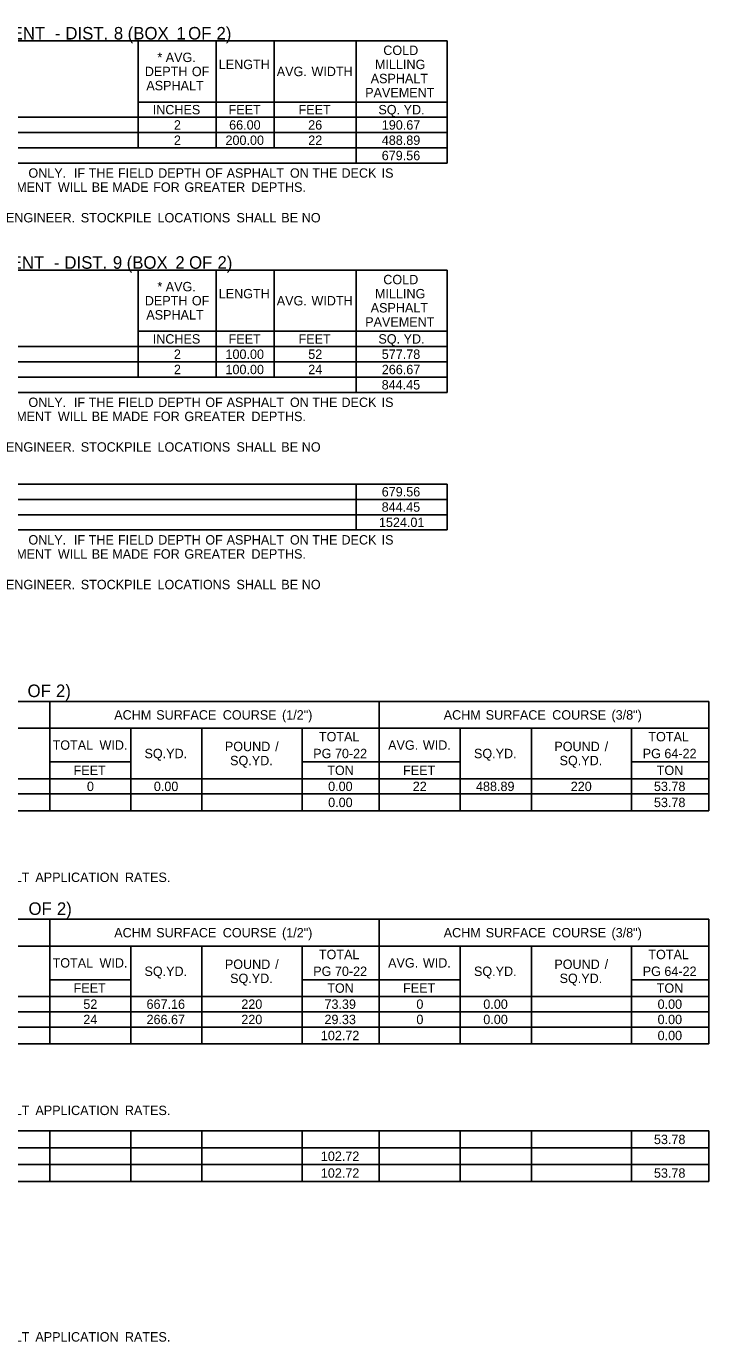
# Model space of a CAD drawing. Extents: x 544420 to 1930787, y -1947044 to 596640.
# Drawn here: x 546901 to 547336, y -1946895 to -1946055 of the extents above; entities that cross this region are included whole.
import ezdxf

# ---------------------------------------------------------------- set-up
doc = ezdxf.new("R2010")
doc.units = 0
doc.layers.add('Default', color=7, linetype='Continuous')

msp = doc.modelspace()

# ---------------------------------------------------------------- linework, layer by layer
at = {"layer": 'Default'}
for p, q in [((546578.54, -1946064.79), (547169.39, -1946064.79)), ((546578.54, -1946064.79), (547169.39, -1946064.79)), ((546972.44, -1946133.04), (546972.44, -1946064.79)), ((547022.16, -1946133.04), (547022.16, -1946064.79)), ((547059.21, -1946133.04), (547059.21, -1946064.79)), ((547111.38, -1946142.79), (547111.38, -1946064.79)), ((547169.39, -1946142.79), (547169.39, -1946064.79)), ((546972.44, -1946103.79), (547059.21, -1946103.79)), ((546972.44, -1946103.79), (547022.16, -1946103.79)), ((547022.16, -1946103.79), (547169.39, -1946103.79)), ((547059.21, -1946113.54), (547059.21, -1946103.79)), ((546578.54, -1946113.54), (547169.39, -1946113.54)), ((546778.41, -1946123.29), (547169.39, -1946123.29)), ((546578.54, -1946133.04), (547169.39, -1946133.04)), ((546578.54, -1946133.04), (547169.39, -1946133.04)), ((546578.54, -1946142.79), (547169.39, -1946142.79)), ((546578.54, -1946211.04), (547169.39, -1946211.04)), ((546578.54, -1946211.04), (547169.39, -1946211.04)), ((546972.44, -1946279.29), (546972.44, -1946211.04)), ((547022.16, -1946279.29), (547022.16, -1946211.04)), ((547059.21, -1946279.29), (547059.21, -1946211.04)), ((547111.38, -1946289.04), (547111.38, -1946211.04)), ((547169.39, -1946289.04), (547169.39, -1946211.04)), ((546972.44, -1946250.04), (547059.21, -1946250.04)), ((546972.44, -1946250.04), (547022.16, -1946250.04)), ((547022.16, -1946250.04), (547169.39, -1946250.04)), ((547059.21, -1946259.79), (547059.21, -1946250.04)), ((546578.54, -1946259.79), (547169.39, -1946259.79)), ((546578.54, -1946269.54), (547169.39, -1946269.54)), ((546578.54, -1946279.29), (547169.39, -1946279.29)), ((546578.54, -1946289.04), (547169.39, -1946289.04)), ((546578.54, -1946347.54), (547169.39, -1946347.54)), ((546578.54, -1946347.54), (547169.39, -1946347.54)), ((547111.38, -1946376.79), (547111.38, -1946347.54)), ((547169.39, -1946376.79), (547169.39, -1946347.54)), ((546578.54, -1946357.29), (547169.39, -1946357.29)), ((546578.54, -1946367.04), (547169.39, -1946367.04)), ((546578.54, -1946376.79), (547169.39, -1946376.79)), ((546342.21, -1946486.24), (547336.23, -1946486.24)), ((546916, -1946555.95), (546916, -1946486.24)), ((547126.11, -1946486.24), (547336.23, -1946486.24)), ((547126.11, -1946555.95), (547126.11, -1946486.24)), ((547336.23, -1946555.95), (547336.23, -1946486.24)), ((546753.66, -1946503.3), (547336.23, -1946503.3)), ((546967.68, -1946503.3), (547013.01, -1946503.3)), ((546967.68, -1946555.95), (546967.68, -1946503.3)), ((547013.01, -1946555.95), (547013.01, -1946503.3)), ((547076.88, -1946555.95), (547076.88, -1946503.3)), ((547177.79, -1946503.3), (547223.13, -1946503.3)), ((547177.79, -1946555.95), (547177.79, -1946503.3)), ((547223.13, -1946555.95), (547223.13, -1946503.3)), ((547286.99, -1946555.95), (547286.99, -1946503.3)), ((546916, -1946524.75), (546967.68, -1946524.75)), ((546916, -1946535.47), (546916, -1946524.75)), ((546967.68, -1946535.47), (546967.68, -1946524.75)), ((547076.88, -1946524.75), (547177.79, -1946524.75)), ((547126.11, -1946535.47), (547126.11, -1946524.75)), ((547177.79, -1946535.47), (547177.79, -1946524.75)), ((547286.99, -1946524.75), (547336.23, -1946524.75)), ((546342.21, -1946535.47), (547336.23, -1946535.47)), ((546847.75, -1946535.47), (546967.68, -1946535.47)), ((546967.68, -1946535.47), (547177.79, -1946535.47)), ((547177.79, -1946535.47), (547336.23, -1946535.47)), ((546342.21, -1946545.22), (547336.23, -1946545.22)), ((546342.21, -1946545.22), (547336.23, -1946545.22)), ((546342.21, -1946555.95), (547336.23, -1946555.95)), ((546342.21, -1946625.17), (547336.23, -1946625.17)), ((546916, -1946704.64), (546916, -1946625.17)), ((547126.11, -1946625.17), (547336.23, -1946625.17)), ((547126.11, -1946704.64), (547126.11, -1946625.17)), ((547336.23, -1946704.64), (547336.23, -1946625.17)), ((546753.66, -1946642.24), (547336.23, -1946642.24)), ((546967.68, -1946642.24), (547013.01, -1946642.24)), ((546967.68, -1946704.64), (546967.68, -1946642.24)), ((547013.01, -1946704.64), (547013.01, -1946642.24)), ((547076.88, -1946704.64), (547076.88, -1946642.24)), ((547177.79, -1946642.24), (547223.13, -1946642.24)), ((547177.79, -1946704.64), (547177.79, -1946642.24)), ((547223.13, -1946704.64), (547223.13, -1946642.24)), ((547286.99, -1946704.64), (547286.99, -1946642.24)), ((546916, -1946663.69), (546967.68, -1946663.69)), ((546916, -1946674.41), (546916, -1946663.69)), ((546967.68, -1946674.41), (546967.68, -1946663.69)), ((547076.88, -1946663.69), (547177.79, -1946663.69)), ((547126.11, -1946674.41), (547126.11, -1946663.69)), ((547177.79, -1946674.41), (547177.79, -1946663.69)), ((547286.99, -1946663.69), (547336.23, -1946663.69)), ((546342.21, -1946674.41), (547336.23, -1946674.41)), ((546847.75, -1946674.41), (546967.68, -1946674.41)), ((546967.68, -1946674.41), (547177.79, -1946674.41)), ((547177.79, -1946674.41), (547336.23, -1946674.41)), ((546342.21, -1946684.16), (547336.23, -1946684.16)), ((546342.21, -1946693.91), (547336.23, -1946693.91)), ((546342.21, -1946704.64), (547336.23, -1946704.64)), ((546342.21, -1946760.21), (547336.23, -1946760.21)), ((546554.76, -1946760.21), (547076.88, -1946760.21)), ((546916, -1946792.39), (546916, -1946760.21)), ((546967.68, -1946792.39), (546967.68, -1946760.21)), ((547013.01, -1946792.39), (547013.01, -1946760.21)), ((547076.88, -1946760.21), (547126.11, -1946760.21)), ((547076.88, -1946792.39), (547076.88, -1946760.21)), ((547126.11, -1946760.21), (547336.23, -1946760.21)), ((547126.11, -1946792.39), (547126.11, -1946760.21)), ((547177.79, -1946792.39), (547177.79, -1946760.21)), ((547223.13, -1946792.39), (547223.13, -1946760.21)), ((547286.99, -1946792.39), (547286.99, -1946760.21)), ((547336.23, -1946792.39), (547336.23, -1946760.21)), ((546342.21, -1946770.94), (547336.23, -1946770.94)), ((546342.21, -1946781.66), (547336.23, -1946781.66)), ((546342.21, -1946792.39), (547336.23, -1946792.39))]:
    msp.add_line(p, q, dxfattribs=at)

# ---------------------------------------------------------------- texts
for s, height, p in [(' PAVEMENT', 8, (546851.26, -1946063.91)), (' DIST.', 8, (546922.99, -1946063.91)), (' 8', 8, (546953.89, -1946063.91)), (' (BOX', 8, (546962.71, -1946063.91)), (' 1', 8, (546993.75, -1946063.91)), (' OF', 8, (547001.25, -1946063.91)), (' 2)', 8, (547019.36, -1946063.91)), (' -', 8, (546916.25, -1946063.91)), ('*', 6, (546984.64, -1946078.29)), (' AVG.', 6, (546987.72, -1946078.29)), ('COLD', 6, (547128.71, -1946073.79)), ('DEPTH', 6, (546976.62, -1946087.29)), (' OF', 6, (547004.4, -1946087.29)), ('LENGTH', 6, (547023.78, -1946082.79)), ('AVG.', 6, (547060.76, -1946087.29)), (' WIDTH', 6, (547080.68, -1946087.29)), ('MILLING', 6, (547123.41, -1946082.79)), ('ASPHALT', 6, (546977.59, -1946096.29)), ('ASPHALT', 6, (547120.67, -1946091.79)), ('PAVEMENT', 6, (547117.18, -1946100.79)), ('INCHES', 6, (546981.67, -1946111.66)), ('FEET', 6, (547030.06, -1946111.66)), ('FEET', 6, (547074.67, -1946111.66)), ('SQ.', 6, (547125.59, -1946111.66)), (' YD.', 6, (547139.45, -1946111.66)), ('2', 6, (546995.19, -1946121.41)), ('66.00', 6, (547030.41, -1946121.41)), ('26', 6, (547080.82, -1946121.41)), ('190.67', 6, (547127.76, -1946121.41)), ('2', 6, (546995.19, -1946131.16)), ('200.00', 6, (547028.08, -1946131.16)), ('22', 6, (547080.86, -1946131.16)), ('488.89', 6, (547127.75, -1946131.16)), ('679.56', 6, (547127.72, -1946140.91)), (' ONLY.', 6, (546900.16, -1946152.09)), ('  IF', 6, (546926.91, -1946152.09)), (' THE', 6, (546938.63, -1946152.09)), (' FIELD', 6, (546957.28, -1946152.09)), (' DEPTH', 6, (546982.92, -1946152.09)), (' OF', 6, (547012.99, -1946152.09)), (' ASPHALT', 6, (547026.57, -1946152.09)), (' ON', 6, (547066.94, -1946152.09)), (' THE', 6, (547081.16, -1946152.09)), (' DECK', 6, (547099.81, -1946152.09)), (' IS', 6, (547125.41, -1946152.09)), (' PAYMENT', 6, (546876.27, -1946161.09)), (' WILL', 6, (546918.96, -1946161.09)), (' BE', 6, (546940.55, -1946161.09)), (' MADE', 6, (546953.62, -1946161.09)), (' FOR', 6, (546979.72, -1946161.09)), (' GREATER', 6, (546999.63, -1946161.09)), (' DEPTHS.', 6, (547042.38, -1946161.09)), (' ENGINEER.', 6, (546885.84, -1946180.59)), (' STOCKPILE', 6, (546933.56, -1946180.59)), (' LOCATIONS', 6, (546982.5, -1946180.59)), (' SHALL', 6, (547032.83, -1946180.59)), (' BE', 6, (547061.43, -1946180.59)), (' NO', 6, (547074.49, -1946180.59)), (' PAVEMENT', 8, (546850.64, -1946210.16)), (' -', 8, (546915.63, -1946210.16)), (' DIST.', 8, (546922.38, -1946210.16)), (' 9', 8, (546953.28, -1946210.16)), (' (BOX', 8, (546962.08, -1946210.16)), (' 2', 8, (546993.11, -1946210.16)), (' OF', 8, (547001.87, -1946210.16)), (' 2)', 8, (547019.98, -1946210.16)), ('COLD', 6, (547128.71, -1946220.04)), ('*', 6, (546984.64, -1946224.54)), (' AVG.', 6, (546987.72, -1946224.54)), ('LENGTH', 6, (547023.78, -1946229.04)), ('MILLING', 6, (547123.41, -1946229.04)), ('DEPTH', 6, (546976.62, -1946233.54)), (' OF', 6, (547004.4, -1946233.54)), ('AVG.', 6, (547060.76, -1946233.54)), (' WIDTH', 6, (547080.68, -1946233.54)), ('ASPHALT', 6, (547120.67, -1946238.04)), ('ASPHALT', 6, (546977.59, -1946242.54)), ('PAVEMENT', 6, (547117.18, -1946247.04)), ('INCHES', 6, (546981.67, -1946257.91)), ('FEET', 6, (547030.06, -1946257.91)), ('FEET', 6, (547074.67, -1946257.91)), ('SQ.', 6, (547125.59, -1946257.91)), (' YD.', 6, (547139.45, -1946257.91)), ('2', 6, (546995.19, -1946267.66)), ('100.00', 6, (547028.08, -1946267.66)), ('52', 6, (547080.86, -1946267.66)), ('577.78', 6, (547127.75, -1946267.66)), ('2', 6, (546995.19, -1946277.41)), ('100.00', 6, (547028.08, -1946277.41)), ('24', 6, (547080.84, -1946277.41)), ('266.67', 6, (547127.76, -1946277.41)), ('844.45', 6, (547127.69, -1946287.16)), (' ONLY.', 6, (546900.16, -1946298.34)), ('  IF', 6, (546926.91, -1946298.34)), (' THE', 6, (546938.63, -1946298.34)), (' FIELD', 6, (546957.28, -1946298.34)), (' DEPTH', 6, (546982.92, -1946298.34)), (' OF', 6, (547012.99, -1946298.34)), (' ASPHALT', 6, (547026.57, -1946298.34)), (' ON', 6, (547066.94, -1946298.34)), (' THE', 6, (547081.16, -1946298.34)), (' DECK', 6, (547099.81, -1946298.34)), (' IS', 6, (547125.41, -1946298.34)), (' PAYMENT', 6, (546876.27, -1946307.34)), (' WILL', 6, (546918.96, -1946307.34)), (' BE', 6, (546940.55, -1946307.34)), (' MADE', 6, (546953.62, -1946307.34)), (' FOR', 6, (546979.72, -1946307.34)), (' GREATER', 6, (546999.63, -1946307.34)), (' DEPTHS.', 6, (547042.38, -1946307.34)), (' ENGINEER.', 6, (546885.84, -1946326.84)), (' STOCKPILE', 6, (546933.56, -1946326.84)), (' LOCATIONS', 6, (546982.5, -1946326.84)), (' SHALL', 6, (547032.83, -1946326.84)), (' BE', 6, (547061.43, -1946326.84)), (' NO', 6, (547074.49, -1946326.84)), ('679.56', 6, (547127.72, -1946355.41)), ('844.45', 6, (547127.69, -1946365.16)), ('1524.01', 6, (547125.92, -1946374.91)), (' ONLY.', 6, (546900.16, -1946386.09)), ('  IF', 6, (546926.91, -1946386.09)), (' THE', 6, (546938.63, -1946386.09)), (' FIELD', 6, (546957.28, -1946386.09)), (' DEPTH', 6, (546982.92, -1946386.09)), (' OF', 6, (547012.99, -1946386.09)), (' ASPHALT', 6, (547026.57, -1946386.09)), (' ON', 6, (547066.94, -1946386.09)), (' THE', 6, (547081.16, -1946386.09)), (' DECK', 6, (547099.81, -1946386.09)), (' IS', 6, (547125.41, -1946386.09)), (' PAYMENT', 6, (546876.27, -1946395.09)), (' WILL', 6, (546918.96, -1946395.09)), (' BE', 6, (546940.55, -1946395.09)), (' MADE', 6, (546953.62, -1946395.09)), (' FOR', 6, (546979.72, -1946395.09)), (' GREATER', 6, (546999.63, -1946395.09)), (' DEPTHS.', 6, (547042.38, -1946395.09)), (' ENGINEER.', 6, (546885.84, -1946414.59)), (' STOCKPILE', 6, (546933.56, -1946414.59)), (' LOCATIONS', 6, (546982.5, -1946414.59)), (' SHALL', 6, (547032.83, -1946414.59)), (' BE', 6, (547061.43, -1946414.59)), (' NO', 6, (547074.49, -1946414.59)), (' OF', 8, (546898.87, -1946483.41)), (' 2)', 8, (546916.98, -1946483.41)), ('ACHM', 6, (546957.12, -1946497.77)), (' SURFACE', 6, (546981.67, -1946497.77)), (' COURSE', 6, (547024.11, -1946497.77)), (' (1/2")', 6, (547061.9, -1946497.77)), ('ACHM', 6, (547167.24, -1946497.77)), (' SURFACE', 6, (547191.79, -1946497.77)), (' COURSE', 6, (547234.22, -1946497.77)), (' (3/8")', 6, (547272.01, -1946497.77)), ('TOTAL', 6, (546917.81, -1946517.02)), (' WID.', 6, (546945.5, -1946517.02)), ('POUND', 6, (547027.68, -1946517.89)), (' /', 6, (547057.54, -1946517.89)), ('TOTAL', 6, (547087.65, -1946511.66)), ('AVG.', 6, (547131.8, -1946517.02)), (' WID.', 6, (547151.72, -1946517.02)), ('POUND', 6, (547237.79, -1946517.89)), (' /', 6, (547267.66, -1946517.89)), ('TOTAL', 6, (547297.76, -1946511.66)), ('SQ.YD.', 6, (546976.42, -1946522.39)), ('PG', 6, (547084.02, -1946522.39)), (' 70-22', 6, (547095.63, -1946522.39)), ('SQ.YD.', 6, (547186.54, -1946522.39)), ('PG', 6, (547294.14, -1946522.39)), (' 64-22', 6, (547305.74, -1946522.39)), ('FEET', 6, (546931.21, -1946533.11)), ('SQ.YD.', 6, (547031.02, -1946526.89)), ('TON', 6, (547092.98, -1946533.11)), ('FEET', 6, (547141.32, -1946533.11)), ('SQ.YD.', 6, (547241.14, -1946526.89)), ('TON', 6, (547303.09, -1946533.11)), ('0', 6, (546939.71, -1946543.35)), ('0.00', 6, (546982.39, -1946543.35)), ('0.00', 6, (547093.54, -1946543.35)), ('22', 6, (547147.51, -1946543.35)), ('488.89', 6, (547187.83, -1946543.35)), ('220', 6, (547248.27, -1946543.35)), ('53.78', 6, (547301.31, -1946543.35)), ('0.00', 6, (547093.55, -1946553.59)), ('53.78', 6, (547301.31, -1946553.59)), (' ASPHALT', 6, (546864.24, -1946601.36)), (' APPLICATION', 6, (546904.61, -1946601.36)), (' RATES.', 6, (546961.69, -1946601.36)), (' OF', 8, (546899.48, -1946622.35)), (' 2)', 8, (546917.59, -1946622.35)), ('ACHM', 6, (546957.12, -1946636.7)), (' SURFACE', 6, (546981.67, -1946636.7)), (' COURSE', 6, (547024.11, -1946636.7)), (' (1/2")', 6, (547061.9, -1946636.7)), ('ACHM', 6, (547167.24, -1946636.7)), (' SURFACE', 6, (547191.79, -1946636.7)), (' COURSE', 6, (547234.22, -1946636.7)), (' (3/8")', 6, (547272.01, -1946636.7)), ('TOTAL', 6, (547087.65, -1946650.6)), ('TOTAL', 6, (547297.76, -1946650.6)), ('TOTAL', 6, (546917.81, -1946655.96)), (' WID.', 6, (546945.5, -1946655.96)), ('POUND', 6, (547027.68, -1946656.82)), (' /', 6, (547057.54, -1946656.82)), ('AVG.', 6, (547131.8, -1946655.96)), (' WID.', 6, (547151.72, -1946655.96)), ('POUND', 6, (547237.79, -1946656.82)), (' /', 6, (547267.66, -1946656.82)), ('SQ.YD.', 6, (546976.42, -1946661.32)), ('SQ.YD.', 6, (547031.02, -1946665.82)), ('PG', 6, (547084.02, -1946661.32)), (' 70-22', 6, (547095.63, -1946661.32)), ('SQ.YD.', 6, (547186.54, -1946661.32)), ('SQ.YD.', 6, (547241.14, -1946665.82)), ('PG', 6, (547294.14, -1946661.32)), (' 64-22', 6, (547305.74, -1946661.32)), ('FEET', 6, (546931.21, -1946672.05)), ('TON', 6, (547092.98, -1946672.05)), ('FEET', 6, (547141.32, -1946672.05)), ('TON', 6, (547303.09, -1946672.05)), ('52', 6, (546937.4, -1946682.29)), ('667.16', 6, (546977.72, -1946682.29)), ('220', 6, (547038.16, -1946682.29)), ('73.39', 6, (547091.2, -1946682.29)), ('0', 6, (547149.82, -1946682.29)), ('0.00', 6, (547192.5, -1946682.29)), ('0.00', 6, (547303.65, -1946682.29)), ('24', 6, (546937.38, -1946692.04)), ('266.67', 6, (546977.72, -1946692.04)), ('220', 6, (547038.16, -1946692.04)), ('29.33', 6, (547091.2, -1946692.04)), ('0', 6, (547149.82, -1946692.04)), ('0.00', 6, (547192.5, -1946692.04)), ('0.00', 6, (547303.65, -1946692.04)), ('102.72', 6, (547088.89, -1946702.27)), ('0.00', 6, (547303.66, -1946702.27)), (' ASPHALT', 6, (546864.24, -1946750.05)), (' APPLICATION', 6, (546904.61, -1946750.05)), (' RATES.', 6, (546961.69, -1946750.05)), ('53.78', 6, (547301.31, -1946768.57)), ('102.72', 6, (547088.89, -1946779.3)), ('102.72', 6, (547088.89, -1946790.02)), ('53.78', 6, (547301.31, -1946790.02)), (' ASPHALT', 6, (546864.24, -1946894.54)), (' APPLICATION', 6, (546904.61, -1946894.54)), (' RATES.', 6, (546961.69, -1946894.54))]:
    msp.add_text(s, height=height, dxfattribs=at).set_placement(p)

doc.saveas('drawing.dxf')
